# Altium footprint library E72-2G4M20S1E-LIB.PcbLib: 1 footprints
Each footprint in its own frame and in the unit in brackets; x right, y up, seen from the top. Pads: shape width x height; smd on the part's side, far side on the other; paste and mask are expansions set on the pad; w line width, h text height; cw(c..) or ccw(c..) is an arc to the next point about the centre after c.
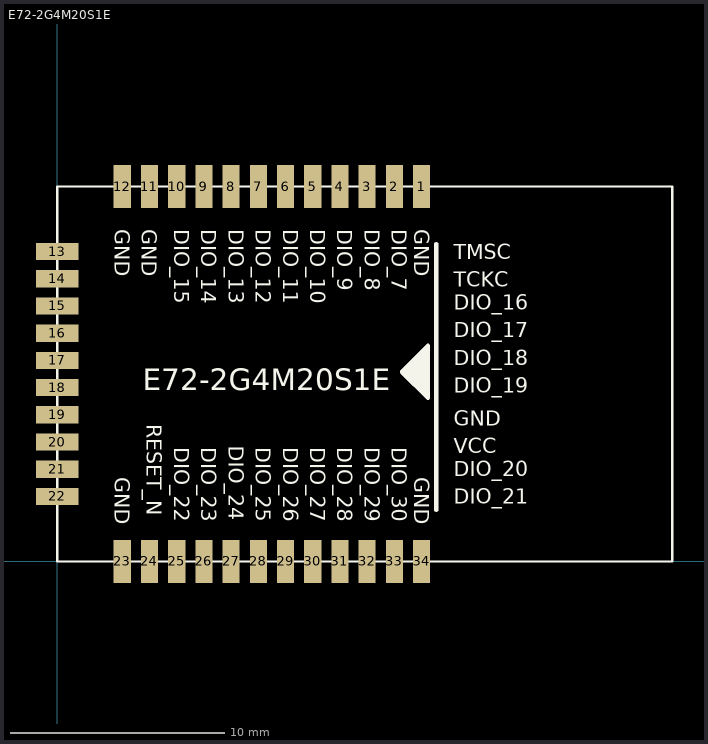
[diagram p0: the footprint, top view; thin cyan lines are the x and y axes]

## E72-2G4M20S1E [mm]
pads (34):
  rect 0.8x2 smd: 1(17.005,17.5) 2(15.735,17.5) 3(14.465,17.5) 4(13.195,17.5) 5(11.925,17.5) 6(10.655,17.5) 7(9.385,17.5) 8(8.115,17.5) 9(6.845,17.5) 10(5.575,17.5) 11(4.305,17.5) 12(3.035,17.5) 23(3.035,0) 24(4.305,0) 25(5.575,0) 26(6.845,0) 27(8.115,0) 28(9.385,0) 29(10.655,0) 30(11.925,0) 31(13.195,0) 32(14.465,0) 33(15.735,0) 34(17.005,0)
  rect 2x0.8 smd: 13(0,14.465) 14(0,13.195) 15(0,11.925) 16(0,10.655) 17(0,9.385) 18(0,8.115) 19(0,6.845) 20(0,5.575) 21(0,4.305) 22(0,3.035)
Top Overlay:
  lines w0.1: 0,0 28.7,0 28.7,17.5 0,17.5 0,0
  lines w0.2: 16.8,9.135 16.9,9.135 ; 16.853,8.982 16.447,8.982 ; 16.893,9.135 16.747,8.988 ; 17.3,9.535 17.3,10.07 16.1,8.87 16.1,8.835 ; 17.691,2.401 17.691,14.817 ; 16.1,8.835 17.3,7.635 17.3,9.835 16.3,8.835 ; 16.1,8.835 16.3,8.835 ; 16.1,8.835 16.249,8.686 16.449,8.686 ; 16.3,8.835 16.447,8.835 ; 16.3,8.835 16.447,8.835 ; 16.447,8.835 16.747,8.535 ; 16.447,8.835 16.447,8.982 ; 16.447,8.982 16.6,9.135 ; 16.447,8.982 16.6,9.135 ; 16.449,8.686 17.2,7.935 17.2,8.235 17.1,8.335 17.1,9.435 17.1,9.635 16.9,9.435 16.9,9.135 ; 16.449,8.686 16.747,8.983 16.747,8.988 ; 16.449,8.686 16.6,8.535 16.747,8.535 ; 16.6,9.135 16.747,8.988 ; 16.6,9.135 16.7,9.235 16.8,9.235 16.9,9.135 ; 16.747,8.535 17,8.282 17,8.135 16.9,8.235 16.9,9.135 ; 16.747,8.535 16.747,8.988
  text "DIO_30" at 15.618,5.334 h0.7
  text "DIO_24" at 7.998,5.4 h0.7
  text "DIO_27" at 11.808,5.334 h0.7
  text "DIO_29" at 14.348,5.334 h0.7
  text "DIO_22" at 5.458,5.334 h0.7
  text "RESET_N" at 4.188,6.4 h0.7
  text "GND" at 16.655,3.934 h0.7
  text "DIO_28" at 13.078,5.334 h0.7
  text "DIO_26" at 10.538,5.334 h0.7
  text "DIO_25" at 9.268,5.334 h0.7
  text "DIO_23" at 6.728,5.334 h0.7
  text "GND" at 2.685,3.934 h0.7
  text "DIO_7" at 15.618,15.5 h0.7
  text "DIO_8" at 14.348,15.5 h0.7
  text "DIO_10" at 11.808,15.5 h0.7
  text "DIO_13" at 7.998,15.5 h0.7
  text "DIO_15" at 5.458,15.5 h0.7
  text "GND" at 3.955,15.5 h0.7
  text "GND" at 16.655,15.5 h0.7
  text "DIO_9" at 13.078,15.5 h0.7
  text "DIO_11" at 10.538,15.5 h0.7
  text "DIO_12" at 9.268,15.5 h0.7
  text "DIO_14" at 6.728,15.5 h0.7
  text "GND" at 2.685,15.5 h0.7
  text "E72-2G4M20S1E" at 4,8 h1
  text "DIO_21" at 18.509,2.685 h0.7
  text "VCC" at 18.509,5.044 h0.7
  text "GND" at 18.509,6.339 h0.7
  text "DIO_18" at 18.509,9.165 h0.7
  text "TCKC" at 18.509,12.819 h0.7
  text "DIO_20" at 18.509,3.981 h0.7
  text "TMSC" at 18.509,14.115 h0.7
  text "DIO_16" at 18.509,11.756 h0.7
  text "DIO_17" at 18.509,10.46 h0.7
  text "DIO_19" at 18.509,7.869 h0.7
